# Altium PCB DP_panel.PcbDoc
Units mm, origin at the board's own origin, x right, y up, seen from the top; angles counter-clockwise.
Board outline 237 x 194 mm, 4 copper layers (Top Layer, (Inserted) Layer 1, (Inserted) Layer 2, Bottom Layer); 0 components, 0 nets, 0 pads, 0 vias.
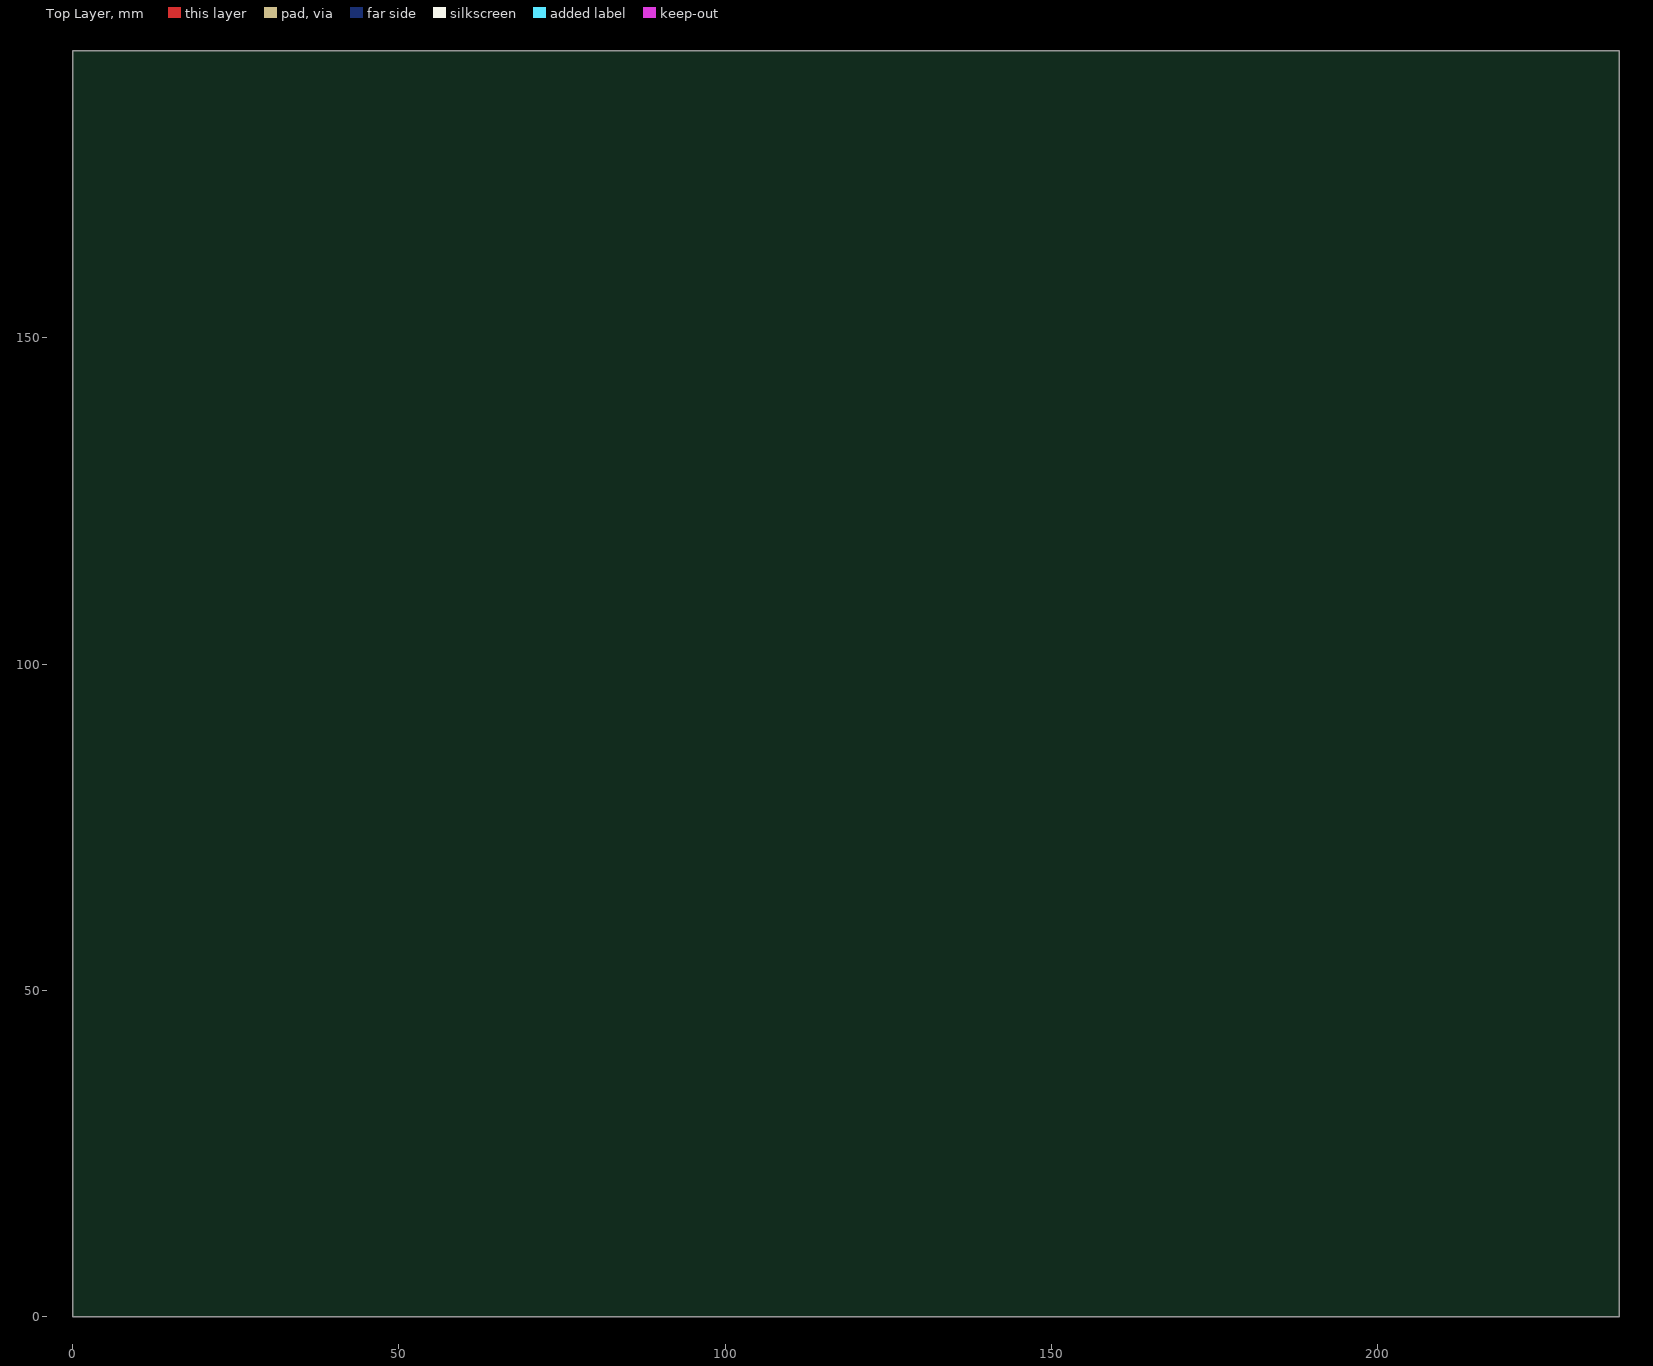
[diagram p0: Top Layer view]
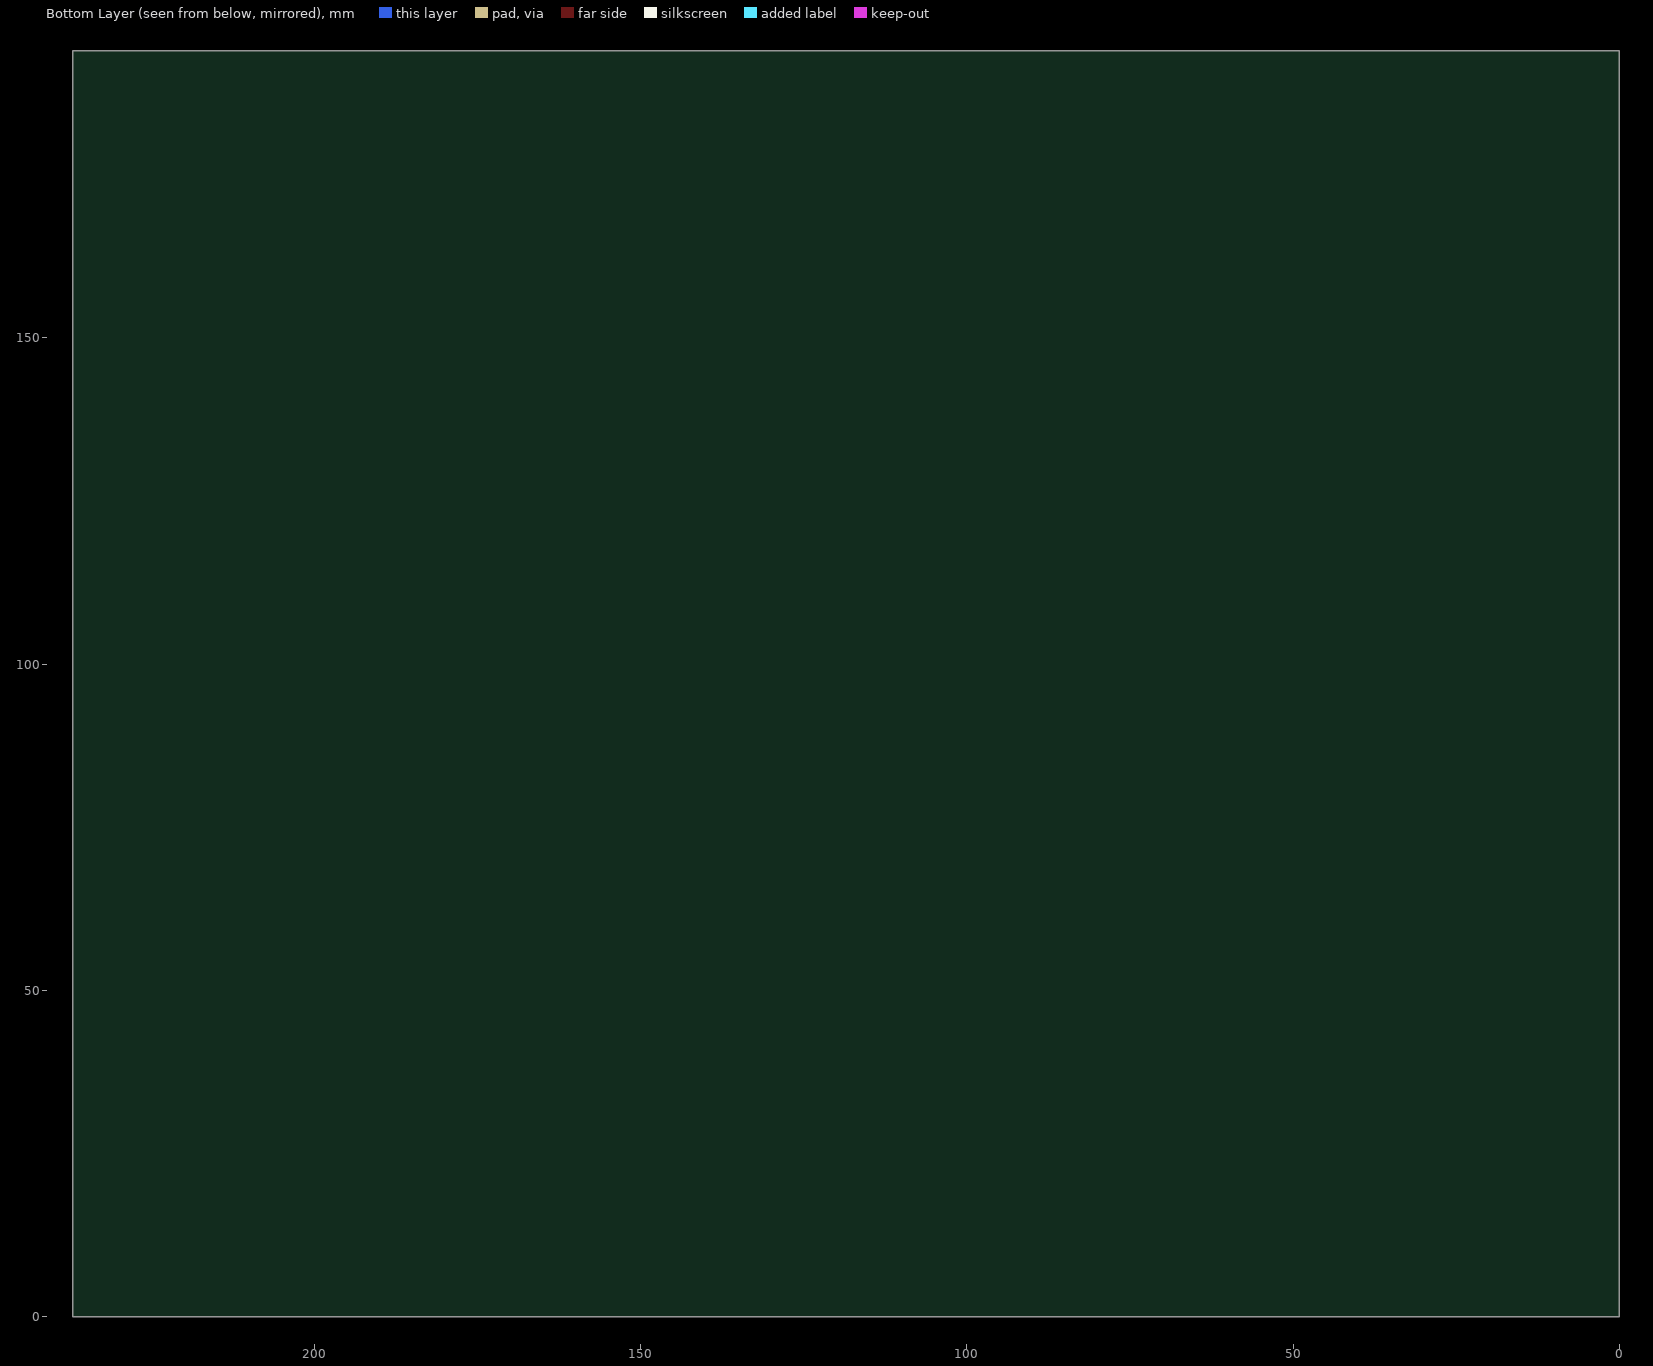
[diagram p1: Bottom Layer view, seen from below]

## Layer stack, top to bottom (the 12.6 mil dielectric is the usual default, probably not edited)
Top Solder: solder mask 0.0102, Solder Resist, Dk 3.5
Top Layer: signal copper 0.0356
(Inserted) Dielectric 3: prepreg 0.32, FR-4, Dk 4.8
(Inserted) Layer 1: signal copper 0.0356
(Inserted) Dielectric 2: prepreg 0.32, FR-4, Dk 4.8
(Inserted) Layer 2: signal copper 0.0356
Dielectric 1: dielectric 0.32, FR-4, Dk 4.8
Bottom Layer: signal copper 0.0356
Bottom Solder: solder mask 0.0102, Solder Resist, Dk 3.5

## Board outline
0,0 237,0 237,194 0,194

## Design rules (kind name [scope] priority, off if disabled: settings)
Clearance [All] p1: gap=0.254 ignorepadtopadclearanceinfootprint=FALSE except(0: Arc-Hole Track-Hole SMDPad-Hole THPad-Hole Via-Hole Fill-Hole Poly-Hole Region-Hole Text-Hole)
PolygonConnect [All] p1: connectstyle=Relief reliefconductorwidth=0.254 reliefentries=4 polygonreliefangle="90 Angle" airgapwidth=0.254
RoutingVias [All] p1: holewidth=0.711 width=1.27 viastyle="Through Hole" minholewidth=0.711 minwidth=1.27 maxholewidth=0.711 maxwidth=1.27
SolderMaskExpansion [All] p1: expansion=0.102
Width [All] p1: maxlimit=0.254 minlimit=0.254 preferedwidth=0.254
30 further rules are at their usual default settings.

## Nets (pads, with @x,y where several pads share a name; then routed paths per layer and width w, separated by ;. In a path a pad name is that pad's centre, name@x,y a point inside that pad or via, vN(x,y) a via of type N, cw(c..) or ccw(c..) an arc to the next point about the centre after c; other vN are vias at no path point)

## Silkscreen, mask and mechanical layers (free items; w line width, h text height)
Mechanical 1:
  the board outline again, w0.1

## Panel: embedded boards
"..\Trigger_Board_ver0\Trigger_Board.PcbDoc" at 10,10, 1 rows x 1 columns, spacing 63.5 x 38.1, rotation 0
"..\Input_Board_ver0\Input_Board_ver0.PcbDoc" at 10,105, 1 rows x 1 columns, spacing 63.5 x 38.1, rotation 0
"..\FPGA_Board_ver0\FPGA_Board.PcbDoc" at 100,10, 1 rows x 1 columns, spacing 63.5 x 38.1, rotation 0
"..\Bias_Power_Supply_ver0\Bias_Power_Supply.PcbDoc" at 105,115, 1 rows x 1 columns, spacing 63.5 x 38.1, rotation 0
